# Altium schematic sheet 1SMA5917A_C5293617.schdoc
size 127 x 101 mm
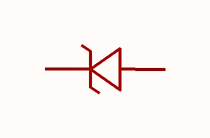
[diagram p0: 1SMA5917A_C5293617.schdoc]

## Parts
D?  1sma5917a_c5293617  [SMAG_L4.3-W2.6-LS5.3-RD]  (value not drawn)

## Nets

Not connected (* = marked no-connect by the designer): D? 1(K) 2(A)

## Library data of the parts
D? = 1sma5917a_c5293617: 二极管配置:1个独立式;稳压值(标称值):4.7V;稳压值(范围值):4.46V~4.94V;耗散功率(Pd):1.5W;; Manufacturer: CJ(江苏长电/长晶); AddInBom: yes; ModelId: 3cd8680d946b497db8ea5837610a9736; ModelTransform: 208.661,102.362,0,0,0,0,0,0,0; Diode Configuration: 1个独立式; Zener Voltage(Nom): 4.7V; Reverse Leakage Current (Ir): 2.5uA@1.5V; Pd - Power Dissipation: 1.5W; Impedance(Zzt): 5Ω; Impedance(Zzk): 500Ω; Operating Junction Temperature Range: -55℃~+150℃; Tolerance: ±5%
